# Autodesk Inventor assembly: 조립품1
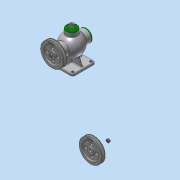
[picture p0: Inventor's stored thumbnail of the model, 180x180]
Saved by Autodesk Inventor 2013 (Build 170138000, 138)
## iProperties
Created: 2018-06
Part Number: 조립품1
Document SubType Name: Assembly
Designer: Administrator
Author: Administrator
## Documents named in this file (19)
- C:\Users\Administrator\Desktop\480612V1018\답안조립품.iam
- C:\Users\Administrator\Desktop\480612V1018\본체.ipt
- C:\Users\Administrator\Desktop\480612V1018\V-벨트풀리.ipt
- C:\Users\Administrator\Desktop\480612V1018\너트 M8.ipt
- C:\Users\Administrator\Desktop\480612V1018\뒤커버.ipt
- C:\Users\Administrator\Desktop\480612V1018\멈춤링 15x1.ipt
- C:\Users\Administrator\Desktop\480612V1018\멈춤링 35x1.6.ipt
- 멈춤링 35x1.6.ipt
- C:\Users\Administrator\Desktop\480612V1018\베어링 6202.ipt
- 베어링 6202.ipt
- C:\Users\Administrator\Desktop\480612V1018\볼트 M4x12.ipt
- C:\Users\Administrator\Desktop\480612V1018\볼트 M4x16.ipt
- C:\Users\Administrator\Desktop\480612V1018\부시.ipt
- C:\Users\Administrator\Desktop\480612V1018\상부커버.ipt
- C:\Users\Administrator\Desktop\480612V1018\슬라이드.ipt
- C:\Users\Administrator\Desktop\480612V1018\앞커버.ipt
- C:\Users\Administrator\Desktop\480612V1018\오일 실 15 30 7.ipt
- C:\Users\Administrator\Desktop\480612V1018\키 4x4x12.ipt
- C:\Users\Administrator\Desktop\480612V1018\편심축.ipt
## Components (2 placed, 1 different names)
1. V-벨트풀리:1
2. V-벨트풀리:2
